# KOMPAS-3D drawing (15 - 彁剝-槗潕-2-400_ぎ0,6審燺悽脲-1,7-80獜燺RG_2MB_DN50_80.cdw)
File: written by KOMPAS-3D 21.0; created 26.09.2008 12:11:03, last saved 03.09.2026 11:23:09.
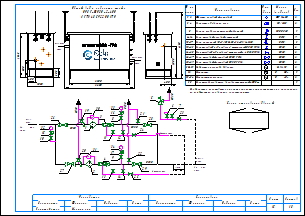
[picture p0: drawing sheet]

Sheets 1-2: A3, landscape

Document properties: Наименование: Макро:21; Автор: RaskoAdmin; Форматы листов документа: 2xA3; Полное имя файла: \\UR38nt01\Departments\КТО\КБ ПУРДГ\Заявки\Прайс-лист на типовые шкафы ГРПШ\ПРДГ_стандарт_20_03_2026\ПРДГ с RG_2MB\ПРДГ-ШУЭО-2-400_до0,6МПа_Рвых-1,7-80кПа_RG_2MB_DN50_80.cdw

Title block, sheet 1: Наименование: Пункт учета газа / ПУГ-Ш-400-Р / ЛГТИ.485922.001ТУ; designation: ЛГТИ.03.4411141; sheet number: 1; Количество листов документа: 2; organisation: ООО "ЭЛЬСТЕР Газэлектроника"; Форматы листов документа: A3; stored path: C:\Рабочие документы\Компас\ПУГ\Схема.cdw; Разработал: Устинов; Проверил: Кошкин; Утвердил: Кошкин
Title block, sheet 2: sheet number: 2; stored path: D:\Рабочие документы\Заявки\ПУРДГ\ПУРДГ-ШУЭО-2-100-Р 4411220.cdw; designation, second copy: ЛГТИ.03.4411141-

Views: Вид 1, Вид 2
Referenced files: wcvoit.frw
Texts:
  Normal
  Вход
  газа
  PDI
  Выход
  Р=     кПа
  DN80
  DN50
  DN20
  Импульс DN20
  ≥5DN
  HYSWLongFangSong
  № на
  схеме
  Усл.
  обозн.
  Марка
  (модель)
  Кол.
  Фильтр газовый фланцевый
  ФГ 16-50
  Регулятор давления газа
  RG/2MB
  Клапан предохранительный сбросной
  КПС DN20
  Кран шаровой газовый латунный
  DN15
  Кран кнопочный VE-РАСКО-НЗ-1,6-G1/2-М20
  Кран шаровой "под приварку" штуцерный DN20 PN16
  Кран шаровой "под приварку" штуцерный п/п DN20 PN16
  Кран шаровой фланцевый DN50 PN16
  Кран шаровой фланцевый DN80 PN16
  Индикатор перепада давления
  Delta 15
  Манометр
  Манометр-напоромер
  Электрообогреватель взрывозащищенный 400Вт
  0...     МПа
  0...     кПа
  Общий вид и габариты шкафа
  ПРДГ-ШУЭО-2-400
  Выход газа
  Вход газа
  Р=        МПа
  logo-rasko-ge.png
  Схема открывания дверей
  Предприятие изготовитель может заменять комплектующие на аналогичные,
  не ухудшающие заявленных характеристик.
  Должность
  Конструктор
  Фамилия
  Подпись
  Дата
  Согласовано
  Максимкин
  Лист
  Листов
  POLYLINE_STYLE_0.18_RGB_0_0_0
  POLYLINE_STYLE_0.50_RGB_0_0_0
  POLYLINE_STYLE_0.34_RGB_0_0_0
  PHANTOM_RGB_0_0_0_SC_1_THICK_0.18
  K5LT_THIN_RGB_0_0_0_THICK_0.18
  K5LT32769_RGB_0_0_0_THICK_0.18
  K5LT12_RGB_0_0_0_SC_1_THICK_0.18
  K5LT_DASHED_RGB_0_0_0_SC_1_THICK_0.18
  ACISOTGL_RGB_0_0_0_SC_0.8_THICK_0.25
  CONTINUOUS_RGB_0_127_31_THICK_0.3
  CONTINUOUS_RGB_0_0_255_THICK_0.35
  CONTINUOUS_RGB_255_0_0_THICK_0.35
  POLYLINE_STYLE_0.25_RGB_0_0_0
  CONTINUOUS_RGB_0_0_0_THICK_0.5
  POLYLINE_STYLE_0.35_RGB_0_0_255
  CONTINUOUS_RGB_0_0_0_THICK_0.4
  CONTINUOUS_RGB_0_0_0_THICK_0.35
  Без оформления
Dimensions and other numbers on the sheet: 1; 2; 3; 4; 5; 10; 27; 28; 29; 23; 8; 12; 19; 20; 21; 22; 25; 24; 30; 31; 15; 16; 26; 6; 7; 11; 14; 13; 33; 1, 2; 3, 4; 6-14; 9; 15-17; 18-23; 24-25; 26-27; 28-29; 30-31; 32; 33-34; 35; 400; 1050; 500; 305; 2300; 1565; 2600; 17; 34; 1000; 4130; 18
